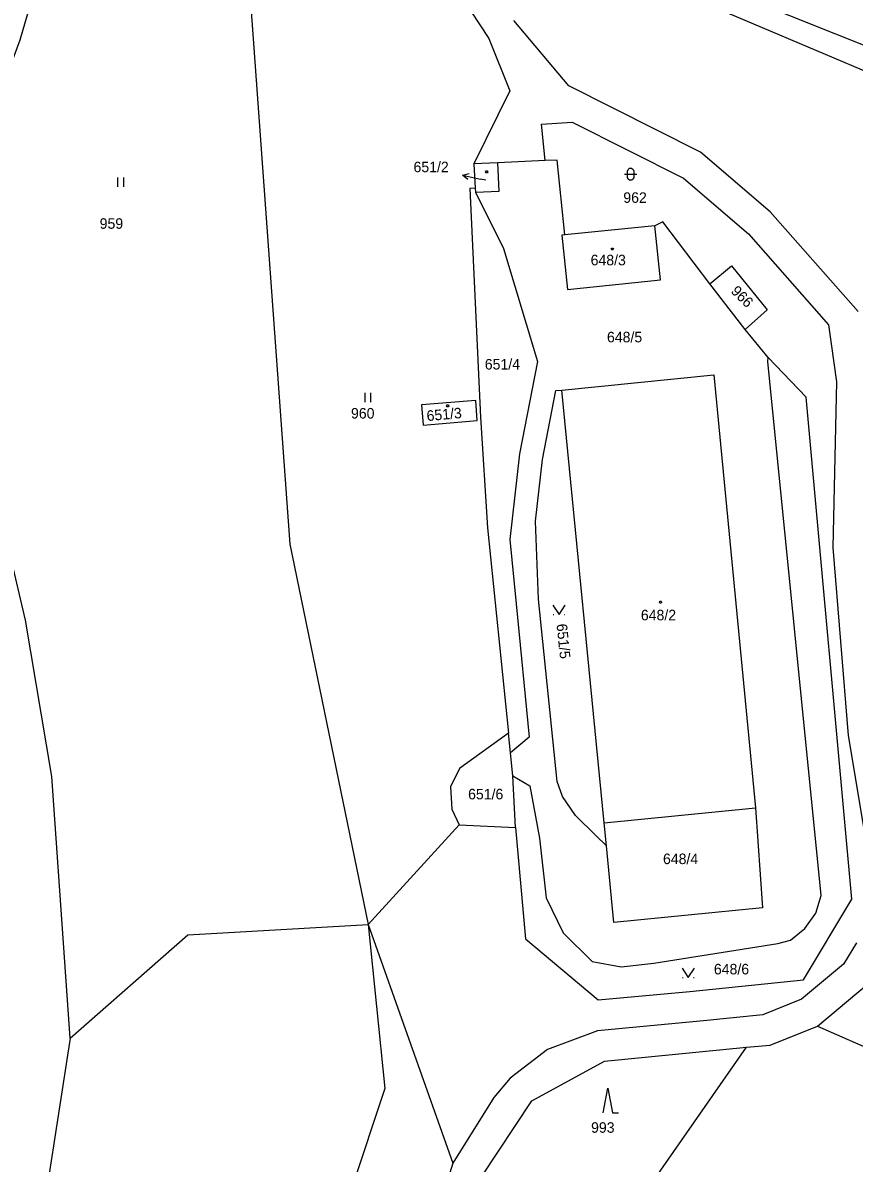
# Model space of a CAD drawing. Extents: x -812394 to -807601, y -1013097 to -1009266.
# Drawn here: x -808967 to -808832.6, y -1011991.8 to -1011807.5 of the extents above; entities that cross this region are included whole.
import ezdxf

# ---------------------------------------------------------------- set-up
doc = ezdxf.new("R2010")
doc.units = 0
for name, color, linetype in [('Default', 7, 'Continuous'), ('KN_HRANICE', 7, 'Continuous'), ('KN_KULTURY', 7, 'Continuous'), ('KN_PARCELY', 7, 'Continuous')]:
    doc.layers.add(name, color=color, linetype=linetype)

# ---------------------------------------------------------------- blocks, each defined once
blk = doc.blocks.new('10292')
at = {"layer": 'Default'}
blk.add_line((0, 3), (0, 0), dxfattribs=at)
blk.add_lwpolyline([(-0.5, 2), (0, 3), (0.5, 2)], dxfattribs=at)
blk = doc.blocks.new('306')
at = {"layer": 'Default'}
for p, q in [((-0.5, 1.5), (-0.5, 0)), ((0.5, 0), (0.5, 1.5))]:
    blk.add_line(p, q, dxfattribs=at)
blk = doc.blocks.new('308')
at = {"layer": 'Default'}
blk.add_lwpolyline([(-0.75, 0), (0, 4), (0.75, 0), (1.75, 0)], dxfattribs=at)
blk = doc.blocks.new('314')
at = {"layer": 'Default'}
for p, q in [((-0.95, 0), (-0.85, 0)), ((0.85, 0), (0.95, 0))]:
    blk.add_line(p, q, dxfattribs=at)
blk.add_lwpolyline([(-1, 1.5), (0, 0), (1, 1.5)], dxfattribs=at)
blk = doc.blocks.new('316')
at = {"layer": 'Default'}
for points in [[(-0.5, 1.5), (-0.4, 1.79), (-0.15, 1.97), (0.16, 1.97), (0.41, 1.79), (0.51, 1.5), (0.51, 0.5), (0.41, 0.21), (0.16, 0.03), (-0.15, 0.03), (-0.4, 0.21), (-0.5, 0.5), (-0.5, 1.5)], [(-1, 1), (0.27, 1), (1, 1)]]:
    blk.add_lwpolyline(points, dxfattribs=at)
blk = doc.blocks.new('402')
at = {"layer": 'Default'}
blk.add_lwpolyline([(0.09, 0.15), (0.18, 0), (0.09, -0.15), (-0.09, -0.15), (-0.18, 0), (-0.09, 0.15), (0.09, 0.15)], dxfattribs=at)

msp = doc.modelspace()

# ---------------------------------------------------------------- linework, layer by layer
at = {"layer": 'KN_HRANICE'}
for p, q in [((-808931.65, -1011783.96), (-808923.83, -1011891.74)), ((-808904.46, -1011790.57), (-808891.7, -1011810.04)), ((-808863.23, -1011798.16), (-808822.56, -1011814.57)), ((-808824.78, -1011817.93), (-808865.49, -1011800.66)), ((-808878.74, -1011817.7), (-808887.62, -1011807.14)), ((-808891.7, -1011810.04), (-808888.3, -1011818.49)), ((-808857.46, -1011828.41), (-808878.74, -1011817.7)), ((-808888.3, -1011818.49), (-808894.08, -1011830.28)), ((-808882.59, -1011829.77), (-808883.19, -1011823.88)), ((-808846.2, -1011838.04), (-808857.46, -1011828.41)), ((-808890.2, -1011830.15), (-808894.08, -1011830.28)), ((-808894.08, -1011830.28), (-808893.88, -1011834.24)), ((-808882.59, -1011829.77), (-808890.2, -1011830.15)), ((-808893.88, -1011834.24), (-808893.84, -1011834.87)), ((-808832.02, -1011854.13), (-808846.2, -1011838.04)), ((-808864.84, -1011840.31), (-808879.4, -1011841.79)), ((-808850.26, -1011857.04), (-808855.95, -1011849.71)), ((-808836.77, -1011856.3), (-808835.53, -1011865.5)), ((-808846.55, -1011861.6), (-808850.26, -1011857.04)), ((-808840.38, -1011868), (-808846.55, -1011861.6)), ((-808835.53, -1011865.5), (-808836.1, -1011892.3)), ((-808873.02, -1011936.78), (-808879.87, -1011866.88)), ((-808833.01, -1011949.12), (-808840.38, -1011868)), ((-808923.83, -1011891.74), (-808911.18, -1011953.22)), ((-808836.1, -1011892.3), (-808833.61, -1011922.64)), ((-808888.16, -1011925.45), (-808888.48, -1011922.27)), ((-808833.61, -1011922.64), (-808829.13, -1011949.41)), ((-808887.78, -1011929.2), (-808888.16, -1011925.45)), ((-808887.35, -1011937.54), (-808887.78, -1011929.2)), ((-808873.02, -1011936.78), (-808848.59, -1011934.33)), ((-808896.46, -1011937.12), (-808911.18, -1011953.22)), ((-808896.46, -1011937.12), (-808887.35, -1011937.54)), ((-808887.35, -1011937.54), (-808885.73, -1011955.49)), ((-808872.67, -1011940.47), (-808873.02, -1011936.78)), ((-808871.48, -1011952.88), (-808872.67, -1011940.47)), ((-808840.81, -1011962.15), (-808833.01, -1011949.12)), ((-808911.18, -1011953.22), (-808897.5, -1011991.75)), ((-808911.18, -1011953.22), (-808908.48, -1011979.67)), ((-808885.73, -1011955.49), (-808874.04, -1011965.37)), ((-808832.28, -1011956.16), (-808834.38, -1011959.6)), ((-808834.38, -1011959.6), (-808841.18, -1011965.26)), ((-808859.18, -1011964.05), (-808840.81, -1011962.15)), ((-808838.58, -1011969.6), (-808830.54, -1011962.92)), ((-808874.04, -1011965.37), (-808859.18, -1011964.05)), ((-808841.18, -1011965.26), (-808847.43, -1011967.77)), ((-808856.99, -1011968.74), (-808874.11, -1011970.38)), ((-808847.43, -1011967.77), (-808856.99, -1011968.74)), ((-808874.11, -1011970.38), (-808882.18, -1011973.42)), ((-808846.23, -1011972.67), (-808838.58, -1011969.6)), ((-808838.58, -1011969.6), (-808820.74, -1011977.44)), ((-808959.35, -1011971.59), (-808963.83, -1012000.81)), ((-808850.04, -1011973.04), (-808846.23, -1011972.67)), ((-808882.18, -1011973.42), (-808888.21, -1011978.01)), ((-808872.97, -1011975.3), (-808850.04, -1011973.04)), ((-808867.42, -1011997.93), (-808850.04, -1011973.04)), ((-808884.75, -1011981.67), (-808872.97, -1011975.3)), ((-808888.21, -1011978.01), (-808890.89, -1011981.16)), ((-808908.48, -1011979.67), (-808935.3, -1012060.33)), ((-808890.89, -1011981.16), (-808897.5, -1011991.75)), ((-808892.86, -1011993.95), (-808884.75, -1011981.67)), ((-808897.5, -1011991.75), (-808915.52, -1012048.78))]:
    msp.add_line(p, q, dxfattribs=at)
for points in [[(-808959.35, -1011971.59), (-808962.28, -1011929.28), (-808966.55, -1011904.05), (-808970.77, -1011886.31), (-808975.49, -1011831.97), (-808967.41, -1011810.26), (-808962, -1011791.72), (-808962.72, -1011776.44), (-808967.65, -1011744.41), (-808976.79, -1011718.1), (-808983.84, -1011699.49)], [(-808883.19, -1011823.88), (-808878.19, -1011823.57), (-808860.25, -1011832.6), (-808849.72, -1011841.61), (-808836.77, -1011856.3)], [(-808893.84, -1011834.87), (-808890.02, -1011834.72), (-808890.2, -1011830.15)], [(-808879.4, -1011841.79), (-808880.63, -1011829.68), (-808882.59, -1011829.77)], [(-808893.88, -1011834.24), (-808894.76, -1011834.28), (-808893.01, -1011871.23)], [(-808893.84, -1011834.87), (-808889.29, -1011844), (-808883.81, -1011862.26), (-808886.75, -1011877.15), (-808888.29, -1011891.01), (-808887.29, -1011901.41), (-808885.17, -1011922.93), (-808888.16, -1011925.45)], [(-808855.95, -1011849.71), (-808863.54, -1011839.67), (-808864.84, -1011840.31)], [(-808879.4, -1011841.79), (-808879.88, -1011841.84), (-808878.95, -1011850.6), (-808863.92, -1011849.05), (-808864.84, -1011840.31)], [(-808855.95, -1011849.71), (-808852.45, -1011846.77), (-808846.73, -1011853.9), (-808850.26, -1011857.04)], [(-808887.78, -1011929.2), (-808885.07, -1011930.82), (-808883.5, -1011939.23), (-808882.39, -1011948.87), (-808879.68, -1011954.55), (-808874.99, -1011959.17), (-808870.31, -1011960.06), (-808865.03, -1011959.42), (-808844.96, -1011956.28), (-808842.95, -1011955.72), (-808840.61, -1011953.86), (-808838.84, -1011951.35), (-808838, -1011948.54), (-808846.62, -1011862.26), (-808846.55, -1011861.6)], [(-808879.87, -1011866.88), (-808855.34, -1011864.41), (-808848.59, -1011934.33)], [(-808872.67, -1011940.47), (-808874.38, -1011938.81), (-808877.69, -1011935.6), (-808879.76, -1011932.53), (-808880.66, -1011930.1), (-808883.68, -1011900.63), (-808884.13, -1011888.05), (-808883.02, -1011878.06), (-808880.88, -1011866.9), (-808879.87, -1011866.88)], [(-808893.01, -1011871.23), (-808891.88, -1011889.12), (-808888.48, -1011922.27)], [(-808888.48, -1011922.27), (-808896.42, -1011927.97), (-808897.88, -1011930.98), (-808897.64, -1011934.58), (-808896.46, -1011937.12)], [(-808848.59, -1011934.33), (-808847.44, -1011950.5), (-808871.48, -1011952.88)], [(-808959.35, -1011971.59), (-808940.32, -1011954.86), (-808911.18, -1011953.22)]]:
    msp.add_lwpolyline(points, dxfattribs=at)
msp.add_lwpolyline([(-808893.79, -1011868.51), (-808902.55, -1011869.21), (-808902.3, -1011872.54), (-808893.56, -1011871.77)], close=True, dxfattribs=at)
at = {"layer": 'KN_PARCELY'}
msp.add_line((-808892.14, -1011832.94), (-808893.03, -1011832.75), dxfattribs=at)

# ---------------------------------------------------------------- block references
at = {"layer": 'KN_KULTURY'}
for name, p in [('306', (-808951.18, -1011833.99)), ('402', (-808892.04, -1011831.59)), ('316', (-808868.78, -1011832.99)), ('402', (-808871.71, -1011844.06)), ('306', (-808911.24, -1011868.78)), ('402', (-808898.34, -1011869.41)), ('314', (-808880.33, -1011903.12)), ('402', (-808863.95, -1011901.12)), ('314', (-808859.45, -1011961.74)), ('308', (-808872.46, -1011983.65))]:
    msp.add_blockref(name, p, dxfattribs=at)
at = {"layer": 'KN_PARCELY', "rotation": 77.750373}
msp.add_blockref('10292', (-808893.03, -1011832.75), dxfattribs=at)

# ---------------------------------------------------------------- texts
at = {"layer": 'KN_PARCELY'}
for s, height, p in [('651/2', 1.7, (-808903.85, -1011831.65)), ('651/2', 0.1, (-808892.27, -1011833.38)), ('962', 1.7, (-808869.95, -1011836.6)), ('959', 1.7, (-808954.56, -1011840.79)), ('648/3', 1.7, (-808875.23, -1011846.69)), ('648/5', 1.7, (-808872.59, -1011859.14)), ('651/4', 1.7, (-808892.33, -1011863.53)), ('960', 1.7, (-808913.95, -1011871.45)), ('648/2', 1.7, (-808867.11, -1011904.05)), ('651/6', 1.7, (-808895.03, -1011932.98)), ('648/4', 1.7, (-808863.54, -1011943.44)), ('648/6', 1.7, (-808855.31, -1011961.26)), ('993', 1.7, (-808875.16, -1011986.85))]:
    msp.add_text(s, height=height, dxfattribs=at).set_placement(p)
for s, rotation, p in [('966', 315.471, (-808852.68, -1011851.01)), ('651/3', 5.099, (-808901.66, -1011871.87)), ('651/5', 275.936, (-808880.75, -1011904.69))]:
    msp.add_text(s, height=1.7, rotation=rotation, dxfattribs=at).set_placement(p)

doc.saveas('drawing.dxf')
